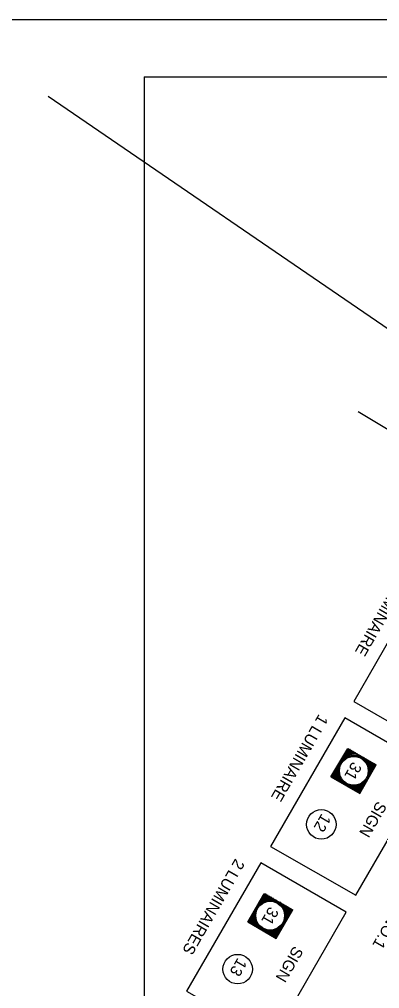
# Model space of a CAD drawing. Extents: x 36 to 2622, y -5330 to 219.
# Drawn here: x 1725.4 to 1819.2, y -4394.4 to -4141.8 of the extents above; entities that cross this region are included whole.
import ezdxf

# ---------------------------------------------------------------- set-up
doc = ezdxf.new("R2010")
doc.units = 0
for name, color, linetype in [('1', 7, 'Continuous'), ('2', 7, 'Continuous'), ('PLT-BNDY', 7, 'Continuous')]:
    doc.layers.add(name, color=color, linetype=linetype)

msp = doc.modelspace()

# ---------------------------------------------------------------- linework, layer by layer
at = {"layer": '1'}
for q in [(2543.86, -4156.83), (1757.86, -4720.83)]:
    msp.add_line((1757.86, -4156.83), q, dxfattribs=at)
at = {"layer": '2'}
for p, q in [((1732.85, -4161.87), (2538.01, -4712.77)), ((1822.73, -4249.58), (1813.61, -4244.08))]:
    msp.add_line(p, q, dxfattribs=at)
for points in [[(1831.73, -4286.08), (1812.48, -4319.58), (1834.73, -4332.45), (1854.11, -4298.95)], [(1810.11, -4323.83), (1790.73, -4357.33), (1812.98, -4370.08), (1832.36, -4336.7)], [(1788.23, -4361.58), (1768.86, -4395.08), (1791.23, -4407.83), (1810.48, -4374.45)]]:
    msp.add_lwpolyline(points, close=True, dxfattribs=at)
for points in [[(1806.48, -4339.2), (1810.86, -4331.83)], [(1810.86, -4331.83), (1818.23, -4336.08)], [(1813.98, -4343.58), (1818.23, -4336.08)], [(1806.48, -4339.2), (1813.98, -4343.58)], [(1784.86, -4376.95), (1789.11, -4369.58)], [(1789.11, -4369.58), (1796.61, -4373.83)], [(1792.23, -4381.33), (1796.61, -4373.83)], [(1784.86, -4376.95), (1792.23, -4381.33)]]:
    msp.add_lwpolyline(points, dxfattribs=at)
for centre, radius in [((1812.45, -4337.65), 4.13), ((1812.45, -4337.65), 3.95), ((1812.45, -4337.65), 3.74), ((1803.99, -4351.59), 3.86), ((1790.66, -4375.38), 4.13), ((1790.66, -4375.38), 3.95), ((1790.66, -4375.38), 3.74), ((1782.2, -4389.32), 3.86)]:
    msp.add_circle(centre, radius, dxfattribs=at)
for centre, radius, start, end in [((1812.45, -4337.65), 4.32, 66.379, 143.0962), ((1812.45, -4337.65), 4.53, 78.594, 131.2253), ((1812.45, -4337.65), 4.73, 84.8374, 125.031), ((1812.45, -4337.65), 4.89, 88.4912, 121.3964), ((1812.45, -4337.65), 5.06, 92.0046, 117.8978), ((1812.45, -4337.65), 5.26, 95.2513, 114.6623), ((1812.45, -4337.65), 5.45, 97.9632, 111.9586), ((1812.45, -4337.65), 5.62, 100.1586, 109.769), ((1812.45, -4337.65), 5.8, 102.2128, 107.7199), ((1812.45, -4337.65), 4.32, 156.9038, 233.0962), ((1812.45, -4337.65), 4.32, 336.379, 53.621), ((1812.45, -4337.65), 4.53, 348.594, 41.406), ((1812.45, -4337.65), 4.73, 354.8374, 35.1626), ((1812.45, -4337.65), 4.89, 358.4912, 31.5088), ((1812.45, -4337.65), 5.06, 2.0046, 27.9954), ((1812.45, -4337.65), 5.26, 5.2513, 24.7486), ((1812.45, -4337.65), 5.45, 7.9632, 22.0368), ((1812.45, -4337.65), 5.62, 10.1586, 19.8414), ((1812.45, -4337.65), 5.8, 12.2128, 17.7872), ((1812.45, -4337.65), 5.8, 192.2801, 197.7199), ((1812.45, -4337.65), 5.62, 190.231, 199.769), ((1812.45, -4337.65), 5.45, 188.0414, 201.9586), ((1812.45, -4337.65), 5.26, 185.3377, 204.6623), ((1812.45, -4337.65), 5.06, 182.1022, 207.8978), ((1812.45, -4337.65), 4.89, 178.6036, 211.3964), ((1812.45, -4337.65), 4.73, 174.969, 215.031), ((1812.45, -4337.65), 4.53, 168.7747, 221.2253), ((1812.45, -4337.65), 4.32, 246.9038, 323.621), ((1812.45, -4337.65), 4.53, 258.7747, 311.406), ((1812.45, -4337.65), 4.73, 264.969, 305.1626), ((1812.45, -4337.65), 4.89, 268.6036, 301.5088), ((1812.45, -4337.65), 5.06, 272.1022, 297.9954), ((1812.45, -4337.65), 5.26, 275.3377, 294.7487), ((1812.45, -4337.65), 5.45, 278.0414, 292.0368), ((1812.45, -4337.65), 5.62, 280.231, 289.8414), ((1812.45, -4337.65), 5.8, 282.2801, 287.7872), ((1790.66, -4375.38), 4.32, 66.379, 143.0962), ((1790.66, -4375.38), 4.53, 78.594, 131.2253), ((1790.66, -4375.38), 4.73, 84.8374, 125.031), ((1790.66, -4375.38), 4.89, 88.4912, 121.3964), ((1790.66, -4375.38), 5.06, 92.0046, 117.8978), ((1790.66, -4375.38), 5.26, 95.2513, 114.6623), ((1790.66, -4375.38), 5.45, 97.9632, 111.9586), ((1790.66, -4375.38), 5.62, 100.1586, 109.769), ((1790.66, -4375.38), 5.8, 102.2128, 107.7199), ((1790.66, -4375.38), 4.32, 156.9038, 233.0962), ((1790.66, -4375.38), 4.32, 336.379, 53.621), ((1790.66, -4375.38), 4.53, 348.594, 41.406), ((1790.66, -4375.38), 4.73, 354.8374, 35.1626), ((1790.66, -4375.38), 4.89, 358.4912, 31.5088), ((1790.66, -4375.38), 5.06, 2.0046, 27.9954), ((1790.66, -4375.38), 5.26, 5.2513, 24.7486), ((1790.66, -4375.38), 5.45, 7.9632, 22.0368), ((1790.66, -4375.38), 5.62, 10.1586, 19.8414), ((1790.66, -4375.38), 5.8, 12.2128, 17.7872), ((1790.66, -4375.38), 5.8, 192.2801, 197.7199), ((1790.66, -4375.38), 5.62, 190.231, 199.769), ((1790.66, -4375.38), 5.45, 188.0414, 201.9586), ((1790.66, -4375.38), 5.26, 185.3377, 204.6623), ((1790.66, -4375.38), 5.06, 182.1022, 207.8978), ((1790.66, -4375.38), 4.89, 178.6036, 211.3964), ((1790.66, -4375.38), 4.73, 174.969, 215.031), ((1790.66, -4375.38), 4.53, 168.7747, 221.2253), ((1790.66, -4375.38), 4.32, 246.9038, 323.621), ((1790.66, -4375.38), 4.53, 258.7747, 311.406), ((1790.66, -4375.38), 4.73, 264.969, 305.1626), ((1790.66, -4375.38), 4.89, 268.6036, 301.5088), ((1790.66, -4375.38), 5.06, 272.1022, 297.9954), ((1790.66, -4375.38), 5.26, 275.3377, 294.7487), ((1790.66, -4375.38), 5.45, 278.0414, 292.0368), ((1790.66, -4375.38), 5.62, 280.231, 289.8414), ((1790.66, -4375.38), 5.8, 282.2801, 287.7872)]:
    msp.add_arc(centre, radius, start, end, dxfattribs=at)
at = {"layer": 'PLT-BNDY'}
msp.add_lwpolyline([(1717.86, -4141.83), (2558.86, -4141.83), (2558.86, -4735.83), (1717.86, -4735.83)], close=True, dxfattribs=at)

# ---------------------------------------------------------------- texts
at = {"layer": '2'}
for s, height, p in [('1 LUMINAIRE', 2.9955, (1825.23, -4284.83)), ('1 LUMINAIRE', 2.9955, (1803.36, -4322.7)), ('31', 2.996, (1812.11, -4335.08)), ('SIGN STRUCTURE NO.1', 2.9955, (1840.23, -4343.08)), ('SIGN', 2.996, (1818.61, -4345.33)), ('12', 2.996, (1804.11, -4348.58)), ('2 LUMINAIRES', 2.9955, (1781.61, -4360.33)), ('31', 2.996, (1790.48, -4372.83)), ('SIGN', 2.996, (1796.86, -4383.08)), ('13', 2.996, (1782.23, -4386.2))]:
    msp.add_text(s, height=height, rotation=240, dxfattribs=at).set_placement(p)

doc.saveas('drawing.dxf')
